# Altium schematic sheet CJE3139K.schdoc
size 127 x 101 mm
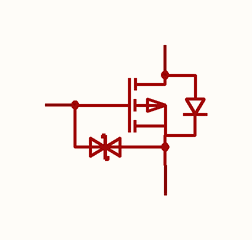
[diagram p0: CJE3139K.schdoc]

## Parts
Q?  cje3139k  [SC-75-3_L1.6-W0.8-P1.00-LS1.7-BR]  (value not drawn)

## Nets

Not connected (* = marked no-connect by the designer): Q? 1(G) 2(S) 3(D)

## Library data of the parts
Q? = cje3139k: 数量:1个P沟道;漏源电压(Vdss):20V;连续漏极电流(Id):660mA;导通电阻(RDS(on)):520mΩ@4.5V;耗散功率(Pd):150mW;阈值电压(Vgs(th)):350mV;; Manufacturer: CJ(江苏长电/长晶); AddInBom: yes; ModelId: c91d337f73514bed9e4f5de3964a5f78; ModelName: SC-75-3_L1.6-W0.8-H0.9-LS1.6-P1.0; ModelTransform: 63.48633,62.992,0,180,0,0,0,0.005,0; Number: 1个P沟道; Drain to Source Voltage: 20V; Current - Continuous Drain(Id): 660mA; Pd - Power Dissipation: 150mW; Gate Threshold Voltage (Vgs(th)): 350mV; Input Capacitance(Ciss): 170pF; Reverse Transfer Capacitance (Crss@Vds): 15pF; Type: P沟道; Vgs: ±12V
